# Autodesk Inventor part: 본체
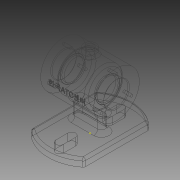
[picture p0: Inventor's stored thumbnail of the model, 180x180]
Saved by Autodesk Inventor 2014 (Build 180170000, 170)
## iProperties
Created: 2017-12
Part Number: 본체
Material: Generic
Document SubType Name: Modeling
Designer: 거성
Density: 1 g/cm^3
Appearance: Default
Author: 거성
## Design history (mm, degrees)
sketch "스케치1"
  geometry: L1 (35, -42.426)-(35, 42.426); L2 (-35, -42.426)-(-35, 42.426); A1 r 55 centre (0, 0) between (-35, -42.426) and (35, -42.426); A2 r 55 centre (0, 0) between (35, 42.426) and (-35, 42.426); 1 further point
  constraints: 4 end point, 4 point on circle, 2 centre point, 1 coincident, 1 concentric, 1 parallel, 1 vertical
  dimensions: "d1" = 70 distance between parallel lines of L2 L1; "d2" = 35 distance from line of point (0, 0) L2; "d3" = 55 radius of A1
extrude "돌출1" new body sketch "스케치1" distance "d4" = 10; taper "d5" = 0 deg
sketch "스케치2"
  geometry: L1 (-35, 42.426)-(-35, -42.426) reference; L2 (35, -42.426)-(35, 42.426) reference; L3 (0, 40)-(0, 24); L4 (-5, 40)-(-5, 24); L5 (5, 24)-(5, 40); A1 r 55 centre (0, 0) between (-35, -42.426) and (35, -42.426) reference; A2 r 55 centre (0, 0) between (35, 42.426) and (-35, 42.426) reference; A3 r 5 centre (0, 40) between (5, 40) and (-5, 40); A4 r 5 centre (0, 24) between (-5, 24) and (5, 24); 1 further point
  constraints: 8 end point, 4 point on circle, 4 tangent, 2 centre point, 2 parallel, 1 midpoint, 1 vertical alignment
  dimensions: "d6" = 16 distance of L5.start L5.end; "d7" = 5 radius of A3; "d8" = 24 distance of L3.end A1.centre
extrude "돌출2" cut sketch "스케치2" distance "d9" = 10; taper "d10" = 0 deg
sketch "스케치3"
  geometry: 1 further point
fillet "모깎기2" dims "d12" = 3
fillet "모깎기3" dims "d13" = 3
sketch "스케치4"
  geometry: L1 (35, 62)-(-35, 62); L2 (-35, 62)-(-35, 92); L3 (-35, 92)-(35, 92); L4 (35, 92)-(35, 62); L5 (33.846, 0)-(-33.846, 0) reference; 3 further points
  constraints: 8 end point, 2 midpoint, 2 parallel, 1 horizontal, 1 perpendicular, 1 vertical alignment
  dimensions: "d14" = 70 distance of L2.end L3.end; "d15" = 30 distance of L1.end L2.end; "d16" = 62 distance between parallel lines of L1 L5
revolve "회전1" sketch "스케치4" stored, may be unused: angle "d17" = 90 deg
sketch "스케치5"
  geometry: L1 (35, 32)-(35, 92) reference; L2 (-35, 32)-(-35, 92) reference; L3 (-35, 92)-(35, 92) reference; L4 (-35, 32)-(35, 32) reference; L5 (-35, 62)-(35, 62); L6 (-35, 78)-(-23, 78); L7 (-23, 78)-(-23, 76); L8 (-23, 76)-(-20, 76); L9 (-20, 76)-(-20, 87); L10 (-20, 87)-(20, 87); L11 (20, 87)-(20, 76); L12 (20, 76)-(23, 76); L13 (23, 76)-(23, 78); L14 (23, 78)-(35, 78); L15 (35, 62)-(35, 78); L16 (-35, 78)-(-35, 62); 1 further point
  constraints: 24 end point, 8 parallel, 3 perpendicular, 2 midpoint, 2 point on line
  dimensions: "d18" = 40 distance of L9.end L10.end; "d19" = 12 distance of L6.start L6.end; "d20" = 12 distance of L13.end L14.end; "d21" = 3 distance of L7.end L8.end; "d22" = 32 diameter of L6 L5; "d23" = 28 diameter of L8 L5; "d24" = 28 diameter of L12 L5; "d25" = 32 diameter of L14 L5; "d26" = 50 diameter of L10 L5
revolve "회전2" sketch "스케치5" stored, may be unused: angle "d27" = 90 deg
fillet "모깎기4" dims "d28" = 0.3
chamfer "모따기1" distance "d29" = 1; stored, may be unused: second distance "d30" = 2, angle "d31" = 45 deg
sketch "스케치6"
  geometry: L1 (-32, -40.988)-(-32, 40.988) reference; L2 (-15, 0)-(15, 0); L3 (-15, 5)-(15, 5); L4 (15, -5)-(-15, -5); A1 r 52 centre (0, 0) between (32, 40.988) and (-32, 40.988) reference; A2 r 5 centre (-15, 0) between (-15, 5) and (-15, -5); A3 r 5 centre (15, 0) between (15, -5) and (15, 5); 1 further point
  constraints: 8 end point, 4 point on circle, 4 tangent, 2 centre point, 1 coincident, 1 midpoint, 1 parallel, 1 perpendicular
  dimensions: "d32" = 5 radius of A2; "d33" = 30 distance of L2.end L2.start
extrude "돌출3" join sketch "스케치6" stored distance "d34" = 10; taper "d35" = 0 deg
fillet "모깎기5" dims "d36" = 5
node "작업 평면1"
sketch "스케치7"
  geometry: L1 (-35, 30)-(-35, -30) reference; C1 r 8 at (0, 0); 1 further point
  constraints: 1 centre point, 1 coincident
  dimensions: "d38" = 16 diameter of C1
extrude "돌출4" join sketch "스케치7" stored distance "d39" = 18.575; taper "d40" = 0 deg
sketch "스케치8"
  geometry: C1 r 8 at (0, 0) reference; C2 r 4 at (0, 0)
  constraints: 1 centre point, 1 coincident
  dimensions: "d41" = 8 diameter of C2
extrude "돌출5" cut sketch "스케치8" stored distance "d42" = 10; taper "d43" = 0 deg
chamfer "모따기2" distance "d44" = 1; stored, may be unused: second distance "d45" = 2, angle "d46" = 45 deg
sketch "스케치9" dims "d47" = 46
  geometry: C1 r 30 at (0, 0) reference; C2 r 17 at (0, 0) reference; 3 further points
  constraints: 2 vertical alignment, 1 coincident, 2 other
hole "구멍1" sketch "스케치9" at (0, 23) diameter "d48" = 3.242; stored, may be unused: countersink angle "d52" = 90 deg, drill point angle "d54" = 118 deg; dims "d49" = 8, "d50" = 4, "d51" = 2, "d53" = 10
fillet "모깎기6" dims "d58" = 3
node "작업 평면2"
sketch "스케치10"
  geometry: L1 (-35, 92)-(35, 92) reference; L2 (-35, 32)-(-35, 92) reference; 2 further points
  constraints: 1 other
  dimensions: "d60" = 35 distance from line of L2 point (0, 62); "d61" = 30 distance from line of L1 point (0, 62)
feature "엠보싱1" sketch "스케치10" dims "d1" = 70, "d2" = 35, "d3" = 55, "d62" = 0.5, "d63" = 0
fillet "모깎기7" dims "d64" = 3
node "솔리드1"
mirror "대칭1"
pattern_circular "원형 패턴1" dims angle "d56" = 360 deg
mirror "대칭2"
node "투영된 루프1"
other parameters: "d37" = 99, "d59" = 45
